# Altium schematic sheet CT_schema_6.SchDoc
size 278 x 170 mm
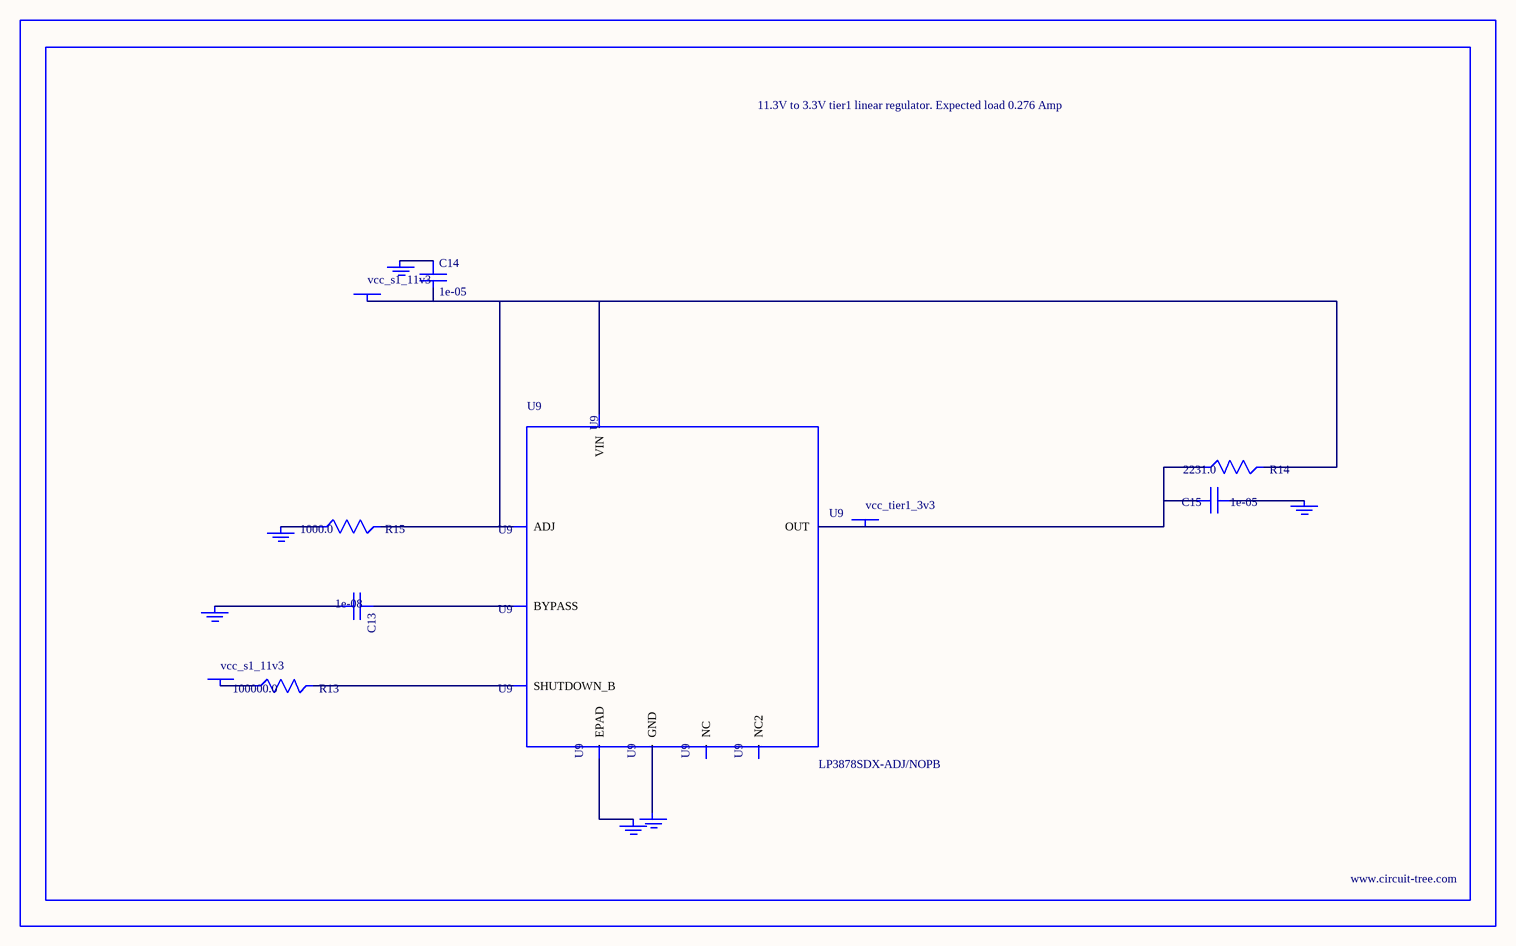
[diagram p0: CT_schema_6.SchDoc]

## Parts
BORDER5  (no value)
C13  1e-08  [C0402]
C14  1e-05  [C1210]
C15  1e-05  [C1210]
GND_INSTANCE_5_0  (no value)
GND_INSTANCE_5_1  (no value)
GND_INSTANCE_5_2  (no value)
GND_INSTANCE_5_3  (no value)
GND_INSTANCE_5_4  (no value)
GND_INSTANCE_5_5  (no value)
POWER_INSTANCE_5_0  vcc_s1_11v3
POWER_INSTANCE_5_1  vcc_s1_11v3
POWER_INSTANCE_5_2  vcc_tier1_3v3
R13  100000.0  [R0603]
R14  2231.0  [R0603]
R15  1000.0  [R0603]
U9  LP3878SDX-ADJ/NOPB  [WSON-8]

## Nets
NetC13_1: C13.1 U9.1(BYPASS)
NetC13_2: C13.2 GND_INSTANCE_5_0.0(GND)
NetC14_1: C14.1 GND_INSTANCE_5_1.0(GND)
NetC14_2: C14.2 POWER_INSTANCE_5_0.0(PWR) R14.2 R15.2 U9.4(VIN) U9.6(ADJ)
NetC15_1: C15.1 GND_INSTANCE_5_2.0(GND)
NetC15_2: C15.2 POWER_INSTANCE_5_2.0(PWR) R14.1 U9.5(OUT)
NetGND_INSTANCE_5_3_0: GND_INSTANCE_5_3.0(GND) R15.1
NetGND_INSTANCE_5_4_0: GND_INSTANCE_5_4.0(GND) U9.PAD(EPAD)
NetGND_INSTANCE_5_5_0: GND_INSTANCE_5_5.0(GND) U9.3(GND)
NetPOWER_INSTANCE_5_1_0: POWER_INSTANCE_5_1.0(PWR) R13.1
NetR13_2: R13.2 U9.8(SHUTDOWN_B)

Not connected (* = marked no-connect by the designer): U9 2(NC) 7(NC2)

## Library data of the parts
BORDER5 = BORDER_PAGE5
C13 = C0402C103K3RAC
C14 = C1210C106K5PACTU
C15 = GRM32DR61E106MA12L
GND_INSTANCE_5_0-GND_INSTANCE_5_5 = GND
POWER_INSTANCE_5_0-POWER_INSTANCE_5_2 = PWR
R13 = RC0603JR-07100KL
R14 = R14
R15 = RC0603JR-071KL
